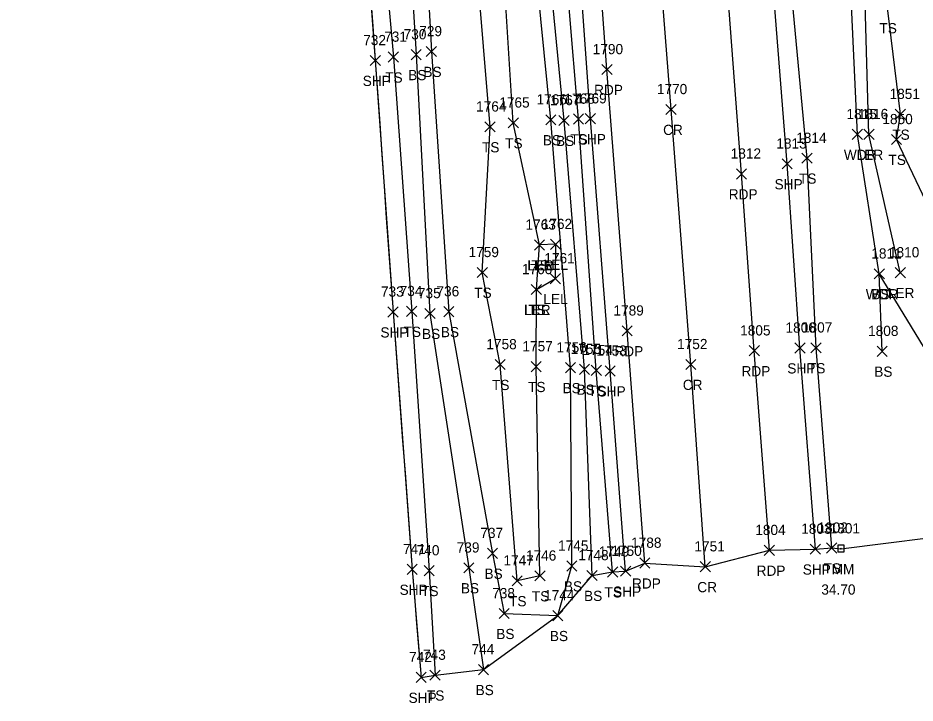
# Model space of a CAD drawing. Extents: x 1650221 to 1650634, y 244606 to 249996.
# Drawn here: x 1650345.8 to 1650521.6, y 244606.2 to 244740.5 of the extents above; entities that cross this region are included whole.
import ezdxf

# ---------------------------------------------------------------- set-up
doc = ezdxf.new("R2010")
doc.units = 0
for name, color, linetype in [('L_A', 7, 'Continuous'), ('L_I', 7, 'Continuous'), ('L_TIC', 7, 'Continuous'), ('LARO', 7, 'Continuous'), ('LAWA', 7, 'Continuous'), ('LELB', 7, 'Continuous'), ('LSOGP', 7, 'Continuous'), ('P_A', 7, 'Continuous'), ('P_I', 7, 'Continuous'), ('P_TIC', 7, 'Continuous'), ('PET', 7, 'Continuous'), ('PRC', 7, 'Continuous'), ('PSP', 7, 'Continuous'), ('S_A', 7, 'Continuous'), ('S_C', 7, 'Continuous'), ('S_I', 7, 'Continuous'), ('SRM', 7, 'Continuous')]:
    doc.layers.add(name, color=color, linetype=linetype)

msp = doc.modelspace()

# ---------------------------------------------------------------- linework, layer by layer
at = {"layer": 'L_TIC'}
for points in [[(1650418.34, 244731.83), (1650420.34, 244733.83)], [(1650420.34, 244731.83), (1650418.34, 244733.83)], [(1650422.8, 244732.3), (1650424.8, 244734.3)], [(1650424.8, 244732.3), (1650422.8, 244734.3)], [(1650425.78, 244732.92), (1650427.78, 244734.92)], [(1650427.78, 244732.92), (1650425.78, 244734.92)], [(1650449.18, 244719.54), (1650451.18, 244721.54)], [(1650451.18, 244719.54), (1650449.18, 244721.54)], [(1650451.78, 244719.4), (1650453.78, 244721.4)], [(1650453.78, 244719.4), (1650451.78, 244721.4)], [(1650454.6, 244719.68), (1650456.6, 244721.68)], [(1650456.6, 244719.68), (1650454.6, 244721.68)], [(1650517.69, 244720.62), (1650519.69, 244722.62)], [(1650519.69, 244720.62), (1650517.69, 244722.62)], [(1650437.29, 244718.15), (1650439.29, 244720.15)], [(1650439.29, 244718.15), (1650437.29, 244720.15)], [(1650441.83, 244718.93), (1650443.83, 244720.93)], [(1650443.83, 244718.93), (1650441.83, 244720.93)], [(1650509.25, 244716.67), (1650511.25, 244718.67)], [(1650511.25, 244716.67), (1650509.25, 244718.67)], [(1650511.53, 244716.67), (1650513.53, 244718.67)], [(1650513.53, 244716.67), (1650511.53, 244718.67)], [(1650516.93, 244715.68), (1650518.93, 244717.68)], [(1650518.93, 244715.68), (1650516.93, 244717.68)], [(1650499.4, 244712.01), (1650501.4, 244714.01)], [(1650501.4, 244712.01), (1650499.4, 244714.01)], [(1650446.97, 244695.01), (1650448.97, 244697.01)], [(1650448.97, 244695.01), (1650446.97, 244697.01)], [(1650446.97, 244695.01), (1650448.97, 244697.01)], [(1650448.97, 244695.01), (1650446.97, 244697.01)], [(1650446.97, 244695.01), (1650448.97, 244697.01)], [(1650448.97, 244695.01), (1650446.97, 244697.01)], [(1650450.15, 244695.13), (1650452.15, 244697.13)], [(1650452.15, 244695.13), (1650450.15, 244697.13)], [(1650435.77, 244689.62), (1650437.77, 244691.62)], [(1650437.77, 244689.62), (1650435.77, 244691.62)], [(1650513.54, 244689.35), (1650515.54, 244691.35)], [(1650515.54, 244689.35), (1650513.54, 244691.35)], [(1650513.54, 244689.35), (1650515.54, 244691.35)], [(1650515.54, 244689.35), (1650513.54, 244691.35)], [(1650517.65, 244689.58), (1650519.65, 244691.58)], [(1650519.65, 244689.58), (1650517.65, 244691.58)], [(1650450.09, 244688.41), (1650452.09, 244690.41)], [(1650452.09, 244688.41), (1650450.09, 244690.41)], [(1650446.36, 244686.28), (1650448.36, 244688.28)], [(1650448.36, 244686.28), (1650446.36, 244688.28)], [(1650446.36, 244686.28), (1650448.36, 244688.28)], [(1650448.36, 244686.28), (1650446.36, 244688.28)], [(1650446.36, 244686.28), (1650448.36, 244688.28)], [(1650448.36, 244686.28), (1650446.36, 244688.28)], [(1650421.93, 244681.99), (1650423.93, 244683.99)], [(1650423.93, 244681.99), (1650421.93, 244683.99)], [(1650425.51, 244681.57), (1650427.51, 244683.57)], [(1650427.51, 244681.57), (1650425.51, 244683.57)], [(1650429.2, 244681.93), (1650431.2, 244683.93)], [(1650431.2, 244681.93), (1650429.2, 244683.93)], [(1650501.16, 244674.85), (1650503.16, 244676.85)], [(1650503.16, 244674.85), (1650501.16, 244676.85)], [(1650514.12, 244674.17), (1650516.12, 244676.17)], [(1650516.12, 244674.17), (1650514.12, 244676.17)], [(1650439.26, 244671.57), (1650441.26, 244673.57)], [(1650441.26, 244671.57), (1650439.26, 244673.57)], [(1650446.32, 244671.17), (1650448.32, 244673.17)], [(1650448.32, 244671.17), (1650446.32, 244673.17)], [(1650453.05, 244670.95), (1650455.05, 244672.95)], [(1650455.05, 244670.95), (1650453.05, 244672.95)], [(1650455.79, 244670.65), (1650457.79, 244672.65)], [(1650457.79, 244670.65), (1650455.79, 244672.65)], [(1650458.1, 244670.43), (1650460.1, 244672.43)], [(1650460.1, 244670.43), (1650458.1, 244672.43)], [(1650504.23, 244635.62), (1650506.23, 244637.62)], [(1650506.23, 244635.62), (1650504.23, 244637.62)], [(1650437.75, 244634.57), (1650439.75, 244636.57)], [(1650439.75, 244634.57), (1650437.75, 244636.57)], [(1650433.12, 244631.73), (1650435.12, 244633.73)], [(1650435.12, 244631.73), (1650433.12, 244633.73)], [(1650453.31, 244632.1), (1650455.31, 244634.1)], [(1650455.31, 244632.1), (1650453.31, 244634.1)], [(1650425.36, 244631.18), (1650427.36, 244633.18)], [(1650427.36, 244631.18), (1650425.36, 244633.18)], [(1650447.06, 244630.15), (1650449.06, 244632.15)], [(1650449.06, 244630.15), (1650447.06, 244632.15)], [(1650447.06, 244630.15), (1650449.06, 244632.15)], [(1650449.06, 244630.15), (1650447.06, 244632.15)], [(1650457.26, 244630.23), (1650459.26, 244632.23)], [(1650459.26, 244630.23), (1650457.26, 244632.23)], [(1650461.3, 244630.92), (1650463.3, 244632.92)], [(1650463.3, 244630.92), (1650461.3, 244632.92)], [(1650442.6, 244629.19), (1650444.6, 244631.19)], [(1650444.6, 244629.19), (1650442.6, 244631.19)], [(1650440.06, 244622.77), (1650442.06, 244624.77)], [(1650442.06, 244622.77), (1650440.06, 244624.77)], [(1650450.56, 244622.37), (1650452.56, 244624.37)], [(1650452.56, 244622.37), (1650450.56, 244624.37)], [(1650426.51, 244610.7), (1650428.51, 244612.7)], [(1650428.51, 244610.7), (1650426.51, 244612.7)], [(1650436.01, 244611.78), (1650438.01, 244613.78)], [(1650438.01, 244611.78), (1650436.01, 244613.78)]]:
    msp.add_lwpolyline(points, dxfattribs=at)
at = {"layer": 'LARO'}
for points in [[(1650518.65, 244690.58), (1650512.53, 244717.67), (1650511.45, 244754.99), (1650506.03, 244803.57), (1650503.39, 244847.38), (1650499.94, 244892.94), (1650496.08, 244933.34), (1650493.78, 244980.84), (1650496.92, 245008.36), (1650497.83, 245048.46), (1650495.91, 245077.72), (1650494.78, 245118.42), (1650491, 245121.86), (1650493.61, 245139.73)], [(1650447.36, 244687.28), (1650451.09, 244689.41), (1650451.15, 244696.13), (1650447.97, 244696.01)], [(1650447.36, 244687.28), (1650447.97, 244696.01)]]:
    msp.add_lwpolyline(points, dxfattribs=at)
at = {"layer": 'LAWA'}
msp.add_lwpolyline([(1650532.93, 244639.7), (1650524.86, 244673.45), (1650514.54, 244690.35), (1650510.25, 244717.67), (1650508.53, 244755.66), (1650503.06, 244803.5), (1650499.99, 244846.46), (1650496.47, 244893.78), (1650492.54, 244932.91), (1650488.72, 244979.52), (1650493.15, 245007.74), (1650492.82, 245049.31), (1650491.93, 245077.75), (1650491, 245121.86)], dxfattribs=at)
at = {"layer": 'LELB'}
for points in [[(1650349.13, 245703.09), (1650351.39, 245660.59), (1650355.99, 245608.05), (1650358.47, 245560.96), (1650362.91, 245508.7), (1650365.76, 245471.06), (1650369.41, 245419.53), (1650373.04, 245367.18), (1650376.89, 245316.29), (1650379.01, 245269.77), (1650383.48, 245220.96), (1650387.1, 245168.26), (1650390.97, 245118.17), (1650394.99, 245063.19), (1650398.03, 245017.1), (1650401.94, 244967.25), (1650403.81, 244936.86), (1650407.34, 244889.23), (1650410.84, 244834.73), (1650414.52, 244785.95), (1650419.34, 244732.83), (1650422.93, 244682.99), (1650426.36, 244632.18), (1650427.51, 244611.7)], [(1650355.71, 245703.22), (1650358.45, 245660.47), (1650361.92, 245609.02), (1650362.95, 245561.76), (1650366.97, 245508.68), (1650370.97, 245471.38), (1650374.07, 245419.38), (1650376.64, 245367.03), (1650382.18, 245316.08), (1650385.68, 245270.43), (1650388.77, 245221.07), (1650390.77, 245168.69), (1650394.69, 245118), (1650401.29, 245063.19), (1650403.89, 245017.69), (1650406.99, 244966.96), (1650408.31, 244937.61), (1650413.12, 244889.16), (1650416.09, 244835.73), (1650420.51, 244786.1), (1650423.8, 244733.3), (1650426.51, 244682.57), (1650434.12, 244632.73), (1650437.01, 244612.78)], [(1650458.26, 244631.23), (1650456.79, 244671.65), (1650452.78, 244720.4), (1650448.37, 244766.08), (1650444.9, 244801.26), (1650441.62, 244837.94), (1650439.87, 244879.23), (1650437.68, 244923.9), (1650433.87, 244972.21), (1650429.49, 245017.89), (1650426.15, 245066.7), (1650422.69, 245123.12), (1650419.86, 245170.84), (1650416.52, 245219.13), (1650411.95, 245271.56), (1650407.71, 245328.35), (1650401.82, 245379.92), (1650396.45, 245433.97), (1650394.84, 245478.56), (1650392.49, 245522.5), (1650389.35, 245551.29), (1650385.12, 245588.75), (1650380.77, 245632.36), (1650373.15, 245685.41)], [(1650462.3, 244631.92), (1650459.1, 244671.43), (1650455.6, 244720.68), (1650451.8, 244765.92), (1650449.21, 244801.88), (1650446.61, 244838.72), (1650443.38, 244880.99), (1650440.04, 244922.8), (1650437.91, 244972.67), (1650433.82, 245018.12), (1650431.01, 245067.65), (1650425.84, 245123.86), (1650424.05, 245171.63), (1650419.6, 245218.92), (1650416.04, 245272.16), (1650411.76, 245328.09), (1650406.63, 245381.03), (1650402.95, 245434.27), (1650400.25, 245479.81), (1650396.41, 245522.79), (1650395.43, 245551.92), (1650392.44, 245589.61), (1650388.27, 245633.5), (1650384.04, 245685.26)], [(1650505.23, 244636.62), (1650502.16, 244675.85), (1650500.4, 244713.01), (1650496.37, 244756.26), (1650493.25, 244801.26), (1650489.44, 244848.53), (1650486.4, 244894.8), (1650483.54, 244931.88), (1650480.85, 244978.69), (1650478.22, 245009.62), (1650475.38, 245046.82), (1650473.75, 245078.48), (1650471.05, 245115.28), (1650468.74, 245140.33)], [(1650447.97, 244696.01), (1650442.83, 244719.93), (1650439.86, 244767.03), (1650436, 244801.8), (1650431.85, 244835.44), (1650431.08, 244878.45), (1650425.94, 244922.68), (1650425.89, 244936.22), (1650425.63, 244949.38), (1650426.44, 244969.3), (1650423.28, 244982.7), (1650423.71, 245016.93), (1650417.3, 245052.81), (1650416.07, 245074.13), (1650417.99, 245100.65), (1650416.66, 245133.49)], [(1650411.89, 244938.28), (1650415.27, 244889.08), (1650419.02, 244835.91), (1650424.03, 244784.72), (1650426.78, 244733.92), (1650430.2, 244682.93), (1650438.75, 244635.57), (1650441.06, 244623.77), (1650451.56, 244623.37), (1650454.31, 244633.1), (1650454.05, 244671.95), (1650450.18, 244720.54), (1650445.7, 244766.1), (1650441.52, 244801.17), (1650438.17, 244837.49), (1650437.28, 244878.95), (1650435.31, 244923.78), (1650434.3, 244938.37)], [(1650524.82, 244692.13), (1650524.3, 244703.21), (1650517.93, 244716.68), (1650518.69, 244721.62), (1650516.17, 244742.48), (1650517.26, 244759.56), (1650514.71, 244782.3), (1650511.3, 244790.99), (1650516.72, 244804.93), (1650514.52, 244824.56), (1650515.45, 244838.01), (1650511.05, 244844.32), (1650513.46, 244857.93), (1650507.41, 244878.18)], [(1650448.06, 244631.15), (1650443.6, 244630.19), (1650440.26, 244672.57), (1650436.77, 244690.62), (1650438.29, 244719.15), (1650434.33, 244767.21)], [(1650515.12, 244675.17), (1650514.54, 244690.35)], [(1650448.06, 244631.15), (1650447.32, 244672.17), (1650447.36, 244687.28)]]:
    msp.add_lwpolyline(points, dxfattribs=at)
at = {"layer": 'LSOGP'}
msp.add_lwpolyline([(1650414.78, 244745.65), (1650415.29, 244738.9), (1650415.79, 244732.16), (1650416.22, 244726), (1650416.66, 244719.84), (1650417.09, 244713.68), (1650417.53, 244707.51), (1650417.96, 244701.35), (1650418.4, 244695.19), (1650418.83, 244689.03), (1650419.27, 244682.87), (1650419.74, 244676.56), (1650420.21, 244670.26), (1650420.68, 244663.95), (1650421.15, 244657.65), (1650421.62, 244651.34), (1650422.09, 244645.04), (1650422.56, 244638.73), (1650423.02, 244632.43), (1650423.46, 244627.13), (1650423.9, 244621.84), (1650424.34, 244616.55), (1650424.78, 244611.26), (1650427.51, 244611.7), (1650437.01, 244612.78), (1650451.56, 244623.37), (1650458.26, 244631.23), (1650462.3, 244631.92), (1650464.84, 244632.07), (1650468.61, 244633.66), (1650480.45, 244632.95), (1650493.02, 244636.16), (1650502.02, 244636.4), (1650505.23, 244636.62), (1650507.02, 244636.48), (1650532.93, 244639.7)], dxfattribs=at)
at = {"layer": 'P_TIC'}
for points in [[(1650414.79, 244731.16), (1650416.79, 244733.16)], [(1650416.79, 244731.16), (1650414.79, 244733.16)], [(1650460.18, 244729.39), (1650462.18, 244731.39)], [(1650462.18, 244729.39), (1650460.18, 244731.39)], [(1650472.75, 244721.56), (1650474.75, 244723.56)], [(1650474.75, 244721.56), (1650472.75, 244723.56)], [(1650456.94, 244719.75), (1650458.94, 244721.75)], [(1650458.94, 244719.75), (1650456.94, 244721.75)], [(1650495.5, 244710.9), (1650497.5, 244712.9)], [(1650497.5, 244710.9), (1650495.5, 244712.9)], [(1650486.56, 244708.93), (1650488.56, 244710.93)], [(1650488.56, 244708.93), (1650486.56, 244710.93)], [(1650418.27, 244681.87), (1650420.27, 244683.87)], [(1650420.27, 244681.87), (1650418.27, 244683.87)], [(1650464.16, 244678.18), (1650466.16, 244680.18)], [(1650466.16, 244678.18), (1650464.16, 244680.18)], [(1650489.06, 244674.27), (1650491.06, 244676.27)], [(1650491.06, 244674.27), (1650489.06, 244676.27)], [(1650498, 244674.82), (1650500, 244676.82)], [(1650500, 244674.82), (1650498, 244676.82)], [(1650460.81, 244670.31), (1650462.81, 244672.31)], [(1650462.81, 244670.31), (1650460.81, 244672.31)], [(1650476.62, 244671.59), (1650478.62, 244673.59)], [(1650478.62, 244671.59), (1650476.62, 244673.59)], [(1650492.02, 244635.16), (1650494.02, 244637.16)], [(1650494.02, 244635.16), (1650492.02, 244637.16)], [(1650501.02, 244635.4), (1650503.02, 244637.4)], [(1650503.02, 244635.4), (1650501.02, 244637.4)], [(1650422.02, 244631.43), (1650424.02, 244633.43)], [(1650424.02, 244631.43), (1650422.02, 244633.43)], [(1650467.61, 244632.66), (1650469.61, 244634.66)], [(1650469.61, 244632.66), (1650467.61, 244634.66)], [(1650479.45, 244631.95), (1650481.45, 244633.95)], [(1650481.45, 244631.95), (1650479.45, 244633.95)], [(1650463.84, 244631.07), (1650465.84, 244633.07)], [(1650465.84, 244631.07), (1650463.84, 244633.07)], [(1650423.78, 244610.26), (1650425.78, 244612.26)], [(1650425.78, 244610.26), (1650423.78, 244612.26)]]:
    msp.add_lwpolyline(points, dxfattribs=at)
at = {"layer": 'PET'}
for points in [[(1650468.61, 244633.66), (1650465.16, 244679.18), (1650461.18, 244730.39), (1650457.78, 244777.29), (1650455.76, 244806.01), (1650453.3, 244838.79), (1650450.33, 244880.04), (1650447.22, 244922.32), (1650443.48, 244972.73), (1650440.49, 245018.18), (1650436.73, 245069.12), (1650432.63, 245123.79), (1650429.44, 245172.68), (1650426.2, 245218.76), (1650422.12, 245272.82), (1650418.28, 245328.28), (1650414.28, 245381.59), (1650410.42, 245434.18), (1650407.03, 245480.26), (1650404.25, 245522.13), (1650401.81, 245552.98), (1650399.16, 245589.27), (1650395.97, 245634.45), (1650392.36, 245685.55)], [(1650493.02, 244636.16), (1650490.06, 244675.27), (1650487.56, 244709.93), (1650484.05, 244756.69), (1650480.76, 244799.76), (1650477.49, 244848.34), (1650473.97, 244894.14), (1650471.41, 244931.35), (1650468.1, 244977.08), (1650466.09, 245009.13), (1650463.32, 245045.8), (1650460.91, 245077.88), (1650458.15, 245114.32), (1650456.62, 245139.84)]]:
    msp.add_lwpolyline(points, dxfattribs=at)
at = {"layer": 'PRC'}
msp.add_lwpolyline([(1650480.45, 244632.95), (1650477.62, 244672.59), (1650473.75, 244722.56), (1650470.31, 244766.82), (1650467.4, 244803.77), (1650467.33, 244807.38), (1650463.88, 244858.27), (1650461.18, 244894.73), (1650457.56, 244949.95), (1650452.93, 245005.14), (1650451.55, 245032.27), (1650447.57, 245085.81), (1650443.28, 245144.22)], dxfattribs=at)
at = {"layer": 'PSP'}
for points in [[(1650345.78, 245703.18), (1650348.63, 245659.65), (1650352.24, 245608.27), (1650356.14, 245560.76), (1650359.83, 245508.67), (1650362.71, 245470.35), (1650366.37, 245419.55), (1650370.09, 245366.17), (1650373.73, 245316.16), (1650376.75, 245269.64), (1650380.21, 245220.67), (1650384.07, 245168.16), (1650387.54, 245117.86), (1650391.85, 245063.26), (1650394.9, 245017.42), (1650398.56, 244967.17), (1650400.8, 244936.49), (1650404.42, 244889.02), (1650408.47, 244833.97), (1650411.77, 244786.13), (1650415.79, 244732.16), (1650419.27, 244682.87), (1650423.02, 244632.43), (1650424.78, 244611.26)], [(1650464.84, 244632.07), (1650461.81, 244671.31), (1650457.94, 244720.75), (1650454.77, 244765.54), (1650451.99, 244802.46), (1650449.34, 244838.71), (1650446.5, 244879.72), (1650443.46, 244922.98), (1650439.98, 244973.19), (1650436.37, 245018.02), (1650433.26, 245068.28), (1650429.09, 245123.84), (1650425.59, 245171.99), (1650422.33, 245218.99), (1650418.38, 245272.19), (1650414.3, 245328), (1650410.4, 245381.3), (1650406.52, 245434.23), (1650403.48, 245480), (1650400.24, 245522.79), (1650398.25, 245552.46), (1650395.41, 245589.43), (1650392.23, 245633.8), (1650388.44, 245685.1)], [(1650502.02, 244636.4), (1650499, 244675.82), (1650496.5, 244711.9), (1650492.99, 244756.49), (1650489.99, 244801), (1650486.51, 244848.42), (1650483.1, 244894.51), (1650480.52, 244931.79), (1650477.17, 244978.41), (1650475.14, 245009.4), (1650472.27, 245046.65), (1650470.2, 245077.93), (1650467.35, 245115.19), (1650465.66, 245140.38)]]:
    msp.add_lwpolyline(points, dxfattribs=at)
at = {"layer": 'SRM'}
for p, q in [((1650507.67, 244637.14), (1650506.42, 244637.14)), ((1650506.42, 244637.14), (1650506.42, 244635.89)), ((1650507.67, 244637.14), (1650506.42, 244637.14)), ((1650506.42, 244637.14), (1650506.42, 244635.89)), ((1650507.67, 244635.89), (1650507.67, 244637.14)), ((1650507.67, 244635.89), (1650507.67, 244637.14)), ((1650506.42, 244635.89), (1650507.67, 244635.89)), ((1650506.42, 244635.89), (1650507.67, 244635.89))]:
    msp.add_line(p, q, dxfattribs=at)
msp.add_circle((1650507.02, 244636.48), 0.0833, dxfattribs=at)

# ---------------------------------------------------------------- texts
at = {"layer": 'L_A'}
for s, p in [('TS', (1650514.58, 244737.48)), ('BS', (1650422.24, 244728.3)), ('BS', (1650425.22, 244728.92)), ('TS', (1650417.74, 244727.83)), ('TS', (1650454.01, 244715.68)), ('TS', (1650517.09, 244716.62)), ('TS', (1650436.7, 244714.15)), ('TS', (1650441.24, 244714.93)), ('BS', (1650448.62, 244715.54)), ('BS', (1650451.22, 244715.4)), ('WDR', (1650507.61, 244712.67)), ('LER', (1650510.12, 244712.67)), ('TS', (1650516.34, 244711.68)), ('TS', (1650498.81, 244708.01)), ('TS', (1650446.38, 244691.01)), ('LEL', (1650448.79, 244691.13)), ('LER', (1650445.55, 244691.01)), ('LEL', (1650445.61, 244691.01)), ('TS', (1650435.18, 244685.62)), ('LEL', (1650448.73, 244684.41)), ('WDR', (1650511.9, 244685.35)), ('BS', (1650512.98, 244685.35)), ('LER', (1650516.23, 244685.58)), ('LER', (1650444.94, 244682.28)), ('LEL', (1650445, 244682.28)), ('TS', (1650445.77, 244682.28)), ('TS', (1650421.34, 244677.99)), ('BS', (1650424.95, 244677.57)), ('BS', (1650428.64, 244677.93)), ('TS', (1650500.57, 244670.85)), ('BS', (1650513.56, 244670.17)), ('TS', (1650438.67, 244667.57)), ('TS', (1650445.73, 244667.17)), ('BS', (1650452.49, 244666.95)), ('BS', (1650455.23, 244666.65)), ('TS', (1650457.51, 244666.43)), ('TS', (1650503.64, 244631.62)), ('BS', (1650437.19, 244630.57)), ('BS', (1650432.56, 244627.73)), ('BS', (1650452.75, 244628.1)), ('TS', (1650424.77, 244627.18)), ('TS', (1650446.47, 244626.15)), ('TS', (1650446.47, 244626.15)), ('BS', (1650456.7, 244626.23)), ('TS', (1650460.71, 244626.92)), ('TS', (1650442.01, 244625.19)), ('BS', (1650439.5, 244618.77)), ('BS', (1650450, 244618.37)), ('TS', (1650425.92, 244606.7)), ('BS', (1650435.45, 244607.78))]:
    msp.add_text(s, height=2, dxfattribs=at).set_placement(p)
at = {"layer": 'L_I'}
for s, p in [('729', (1650424.41, 244736.92)), ('731', (1650417.54, 244735.83)), ('730', (1650421.35, 244736.3)), ('1851', (1650516.56, 244724.62)), ('1765', (1650440.09, 244722.93)), ('1766', (1650447.39, 244723.54)), ('1767', (1650450.04, 244723.4)), ('1768', (1650452.86, 244723.68)), ('1764', (1650435.55, 244722.15)), ('1815', (1650508.12, 244720.67)), ('1816', (1650510.35, 244720.67)), ('1850', (1650515.15, 244719.68)), ('1814', (1650498.27, 244716.01)), ('1763', (1650445.23, 244699.01)), ('1763', (1650445.23, 244699.01)), ('1763', (1650445.23, 244699.01)), ('1762', (1650448.41, 244699.13)), ('1759', (1650434.07, 244693.62)), ('1811', (1650512.98, 244693.35)), ('1811', (1650512.98, 244693.35)), ('1810', (1650516.44, 244693.58)), ('1761', (1650448.92, 244692.41)), ('1760', (1650444.53, 244690.28)), ('1760', (1650444.53, 244690.28)), ('1760', (1650444.53, 244690.28)), ('734', (1650420.57, 244685.99)), ('736', (1650427.78, 244685.93)), ('735', (1650424.15, 244685.57)), ('1807', (1650499.39, 244678.85)), ('1808', (1650512.35, 244678.17)), ('1758', (1650437.56, 244675.57)), ('1757', (1650444.63, 244675.17)), ('1756', (1650451.3, 244674.95)), ('1755', (1650454.09, 244674.65)), ('1754', (1650456.41, 244674.43)), ('737', (1650436.38, 244638.57)), ('1802', (1650502.45, 244639.62)), ('740', (1650423.91, 244635.18)), ('739', (1650431.75, 244635.73)), ('1745', (1650451.61, 244636.1)), ('1749', (1650459.6, 244634.92)), ('1747', (1650440.91, 244633.19)), ('1746', (1650445.31, 244634.15)), ('1746', (1650445.31, 244634.15)), ('1748', (1650455.57, 244634.23)), ('738', (1650438.7, 244626.77)), ('1744', (1650448.87, 244626.37)), ('744', (1650434.65, 244615.78)), ('743', (1650425.15, 244614.7))]:
    msp.add_text(s, height=2, dxfattribs=at).set_placement(p)
at = {"layer": 'P_A'}
for s, p in [('SHP', (1650413.33, 244727.16)), ('RDP', (1650458.67, 244725.39)), ('CR', (1650472.19, 244717.56)), ('SHP', (1650455.48, 244715.75)), ('SHP', (1650494.03, 244706.9)), ('RDP', (1650485.05, 244704.93)), ('SHP', (1650416.8, 244677.87)), ('RDP', (1650462.65, 244674.18)), ('RDP', (1650487.55, 244670.27)), ('SHP', (1650496.53, 244670.82)), ('CR', (1650476.05, 244667.59)), ('SHP', (1650459.35, 244666.31)), ('SHP', (1650499.55, 244631.4)), ('RDP', (1650490.51, 244631.16)), ('RDP', (1650466.1, 244628.66)), ('CR', (1650478.89, 244627.95)), ('SHP', (1650420.56, 244627.43)), ('SHP', (1650462.38, 244627.07)), ('SHP', (1650422.32, 244606.26))]:
    msp.add_text(s, height=2, dxfattribs=at).set_placement(p)
at = {"layer": 'P_I'}
for s, p in [('732', (1650413.43, 244735.16)), ('1790', (1650458.4, 244733.39)), ('1770', (1650470.97, 244725.56)), ('1769', (1650455.19, 244723.75)), ('1813', (1650494.37, 244714.9)), ('1812', (1650485.43, 244712.93)), ('733', (1650416.91, 244685.87)), ('1789', (1650462.46, 244682.18)), ('1806', (1650496.17, 244678.82)), ('1805', (1650487.29, 244678.27)), ('1752', (1650474.93, 244675.59)), ('1753', (1650459.12, 244674.31)), ('1804', (1650490.25, 244639.16)), ('1803', (1650499.25, 244639.4)), ('1788', (1650465.92, 244636.66)), ('741', (1650421.23, 244635.43)), ('1750', (1650462.06, 244635.07)), ('1751', (1650478.33, 244635.95)), ('742', (1650422.42, 244614.26))]:
    msp.add_text(s, height=2, dxfattribs=at).set_placement(p)
at = {"layer": 'S_A'}
msp.add_text('MM', height=2, dxfattribs=at).set_placement((1650505.21, 244631.48))
at = {"layer": 'S_C'}
msp.add_text('34.70', height=2, dxfattribs=at).set_placement((1650503.19, 244627.48))
at = {"layer": 'S_I'}
msp.add_text('1801', height=2, dxfattribs=at).set_placement((1650504.82, 244639.48))

doc.saveas('drawing.dxf')
